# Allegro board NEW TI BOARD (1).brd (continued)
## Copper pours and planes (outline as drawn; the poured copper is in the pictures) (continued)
N992164 on BOTTOM: 186.56,55.23 180.89,55.23 180.89,55.22 180.23,55.22 178.93,53.93 177.18,53.93 177.12,53.87 177.12,52.4 177.15,52.37 178.51,52.37 180.87,54.72 186.52,54.72 186.56,54.76 186.56,55.22
N992182 on BOTTOM: 186.12,59.55 183.29,56.71 175.18,56.71 175.11,56.64 175.11,55.3 175.16,55.26 179.79,55.26 180.05,55.52 186.53,55.52 186.57,55.56 186.57,56.49 188.06,57.99 189.26,57.99 189.52,58.25 189.52,59.08 189.06,59.55
N992267 on BOTTOM: 186.56,54.43 181.51,54.43 175.12,48.03 175.12,42.94 175.2,42.85 176.59,42.85 176.73,42.99 176.73,48.58 182.08,53.92 186.55,53.92 186.56,53.94 186.56,54.42
N992271 on BOTTOM: 179.11,43.16 178.93,43.34 178.93,50.11 180.78,51.96 181.13,51.96 181.36,51.73 181.36,51.49 180.5,50.63 180.5,48.64 180.5,48.64 180.5,43.28 180.39,43.16
N995338 on BOTTOM: 200.92,79.63 199.66,79.63 199.59,79.56 199.59,77.22 198.84,76.46 198.84,75.02 198.9,74.96 200.16,74.96 200.34,75.14 200.34,76.95 201.16,77.77 202.86,77.77 202.93,77.84 202.93,79.19 202.87,79.25 201.3,79.25
N1047887 on BOTTOM: 160.3,118.97 160.42,119.09 160.42,123.73 160.36,123.79 158.4,123.79 158.25,123.64 158.25,118.98 158.26,118.97
N1057020 on BOTTOM: 156.36,122.46 157.13,121.69 157.13,118.88 158.37,117.64 160.83,117.64 162.38,116.09 162.38,111.26 162.2,111.07 161.12,111.07 160.76,111.43 160.76,114.91 160,115.66 157.86,115.66 157.59,115.39 157.56,115.39 157.34,115.17 157.34,108.06 158.72,106.68 158.72,104.86 157.9,104.04 153.38,104.04 151.81,105.62 151.81,120.77 153.49,122.46
N1102671 on TOP: 177.74,114.29 177.74,109.54 176.68,108.48 175.38,108.48 175.07,108.79 175.07,114.39 175.07,114.39 175.3,114.62 177.41,114.62
N1102671 on TOP: 167.86,114.25 168.24,114.25 168.26,114.27 171.12,114.27 171.6,113.79 171.6,109.76 160.92,99.07 155.56,99.07 154.84,99.79 154.84,101.93 155.25,102.35 158.66,102.35 167.09,110.78 167.09,113.48
N1102671 on BOTTOM: 172.2,115.91 174.33,115.91 175.01,115.23 175.01,108.8 175.46,108.35 176.41,108.35 177,108.94 177,119.24 176.81,119.43 170.73,119.43 169.32,118.03 167.36,118.03 167.22,117.89 167.22,110.31 168.23,109.3 170.53,109.3 171.6,110.37 171.6,115.32
N1232683 on BOTTOM: 153.02,65.88 153.32,66.19 161.42,66.19 161.43,66.18 163.11,66.18 165.69,63.61 165.69,61.92 169.6,61.92 169.68,62 169.68,63.21 169.47,63.41 167.96,63.41 163.69,67.68 151.07,67.68 151.07,67.68 148.77,67.68 148.51,67.42 148.51,66.07 148.7,65.88
N1232719 on BOTTOM: 162.55,62.73 162.55,62.73 164.07,61.21 164.07,56.91 165.53,55.45 165.53,46.62 165.86,46.29 167.3,46.29 167.39,46.38 167.39,47.67 167.12,47.93 167.12,56.73 167.01,56.84 165.34,56.84 165.14,57.04 165.14,57.05 164.86,57.32 164.86,62.12 161.93,65.05 160.55,65.05 160.46,64.96 160.46,63.54 160.59,63.41 161.87,63.41
N1232753 on BOTTOM: 164.5,40.91 167.39,40.91 167.63,41.15 167.63,42.3 167.33,42.6 164.92,42.6 163.3,44.21 163.3,59.76 160.18,62.88 155.66,62.88 155.39,63.15 155.39,64.89 155.39,64.97 155.14,65.21 151.29,65.21 151.03,64.96 148.65,64.96 148.53,64.84 148.53,63.39 148.65,63.27 152.29,63.27 152.3,63.26 153.87,63.26 155.21,61.92 159.38,61.92 162.2,59.1 162.2,43.21
N1262247 on BOTTOM: 182.44,60.36 182.44,59.01 182.54,58.91 183.91,58.91 185.37,60.37 189.61,60.37 190.24,59.74 190.86,59.74 191.28,60.16 191.28,60.89 190.69,61.49 183.57,61.49
N1271766 on BOTTOM: 159.87,65.06 156,65.06 155.87,64.93 155.87,63.58 155.97,63.47 159.82,63.47 159.92,63.58 159.92,65
N1473058 on BOTTOM: 202.38,104.88 202.38,103.47 202.38,103.47 202.38,103.01 202.6,102.79 204.48,102.79 205.16,103.47 206.09,103.47 206.81,102.75 208.39,102.75 209,103.36 209,104.31 208.42,104.9 205.76,104.9 205.75,104.91 205.02,104.91 204.63,105.29 202.79,105.29
N1473062 on BOTTOM: 204.64,101.51 204.57,101.58 202.54,101.58 202.29,101.33 202.29,98.12 201.9,97.73 201.9,95.28 202.04,95.14 203.99,95.14 204.04,95.19 204.04,98.35 204.64,98.95
N1473074 on BOTTOM: 210.48,114.22 208.05,114.22 207.88,114.05 207.88,110.66 207.88,110.66 207.88,110.37 206.7,109.19 206.29,108.78 206.29,106.23 206.81,105.71 208.47,105.71 208.97,106.21 208.97,108.29 209.6,108.91 211.98,108.91 212.11,109.05 212.11,112.59 210.99,113.71 210.99,113.71
N1473136 on BOTTOM: 210.51,102.73 209.82,102.03 206.49,102.03 206.15,101.69 206.15,100.35 206.89,99.61 209.54,99.61 209.94,99.21 211.05,99.21 211.13,99.29 211.13,100.32 212.07,101.26 212.07,108.27 212.02,108.32 210.59,108.32 210.51,108.24
N1473188 on BOTTOM: 210.12,97.19 210.16,97.23 210.16,98.24 210.12,98.28 208.79,98.28 208.28,98.28 205.54,95.53 205.54,94.25 205.62,94.17 207.04,94.17 207.13,94.25 207.13,95.7 208.62,97.19
N1473270 on BOTTOM: 211.28,98.23 211.2,98.15 211.2,96.81 211.2,96.36 210.5,95.65 208.09,95.65 208,95.57 208,94.3 208.17,94.13 211.97,94.13 212.14,94.3 212.14,98.15 212.06,98.23
N1626311 on BOTTOM: 40.76,67.2 42.36,67.2 42.44,67.11 42.44,63.68 42.85,63.27 49.2,63.27 50.43,62.04 50.43,61.16 50.43,60.42 51.84,59.01 51.84,52.03 50.84,51.03 49.37,51.03 48.58,51.83 48.58,61.16 48.57,61.16 48.57,61.47 47.89,62.15 42.6,62.15 41.85,61.4 40.69,61.4 40.03,62.06 40.03,63.18 40.58,63.73 40.58,67.02
N1626403 on BOTTOM: 63.81,41.53 62.79,41.53 62.08,40.83 62.08,37.66 64.21,35.53 66.57,35.53 66.71,35.68 66.71,38.08 66.51,38.28 65.53,38.28 64.5,39.32 64.5,40.84
N1626473 on BOTTOM: 47.07,49.95 44.81,49.95 44.12,49.26 44.12,44.6 44.21,44.51 46.4,44.51 46.97,45.07 50.99,45.07 51.53,45.61 51.53,46.93 50.92,47.54 48.87,47.54 47.19,49.22 47.19,49.82
N1626717 on BOTTOM: 39.41,67.21 37.88,67.21 37.59,66.92 37.59,65.48 37.17,65.06 35.08,65.06 34.96,64.94 34.96,63.23 35.07,63.12 37.41,63.12 39.5,65.21 39.5,67.11
N1626863 on BOTTOM: 48.5,38.59 47.55,38.59 47.34,38.38 47.34,36.7 47.24,36.6 47.24,34.74 47.29,34.68 48.97,34.68 49.07,34.78 49.07,36.53 48.66,36.95 48.66,38.43
N1626895 on BOTTOM: 45.99,34.65 44.28,34.65 44.18,34.75 44.18,36.93 45.25,38 46.13,38 46.46,37.68 46.46,36.95 46.08,36.58 46.08,34.74
N1626895 on BOTTOM: 41.37,42.66 37.66,42.66 37.59,42.73 36.99,42.73 36.81,42.55 36.81,42.05 37.09,41.77 37.52,41.77 37.71,41.96 41.36,41.96 41.41,42.01 41.41,42.62
N1626923 on BOTTOM: 42.38,43.93 39.24,43.93 39.18,43.87 39.18,43.29 39.23,43.24 42,43.24 42.27,42.97 42.27,41.87 41.16,40.76 41.16,37.85 40.99,37.67 40.99,36.31 41.07,36.24 42.51,36.24 42.66,36.39 42.66,41.3 42.98,41.62 42.98,43.33
N1627019 on BOTTOM: 41.71,49.26 37.81,49.26 37.69,49.14 37.69,47.99 39.17,46.51 39.17,45.89 39.24,45.81 41.34,45.81 41.49,45.96 41.49,47.49 41.8,47.8 41.8,49.18
N1627749 on BOTTOM: 55.24,48.03 53.49,48.03 53.35,47.88 53.35,44.95 53.88,44.41 55.18,44.41 55.41,44.63 55.41,47.87
N1658391 on TOP: 121.04,68.6 121.02,68.61 121.02,82.91 120.54,83.38 116.42,83.38 115.75,82.72 115.75,74.2 115.69,74.15 115.69,66.36 115.7,66.35 114.83,65.48 114.83,61.22 115.62,60.43 117.04,60.43 117.05,60.43 117.57,60.43 118.31,61.18 118.31,63.74 121.04,66.47
N1658391 on BOTTOM: 120.17,83.01 117.73,83.01 116.7,81.98 116.7,71.79 115.51,70.61 114.04,70.61 113.91,70.47 113.91,68.12 113.91,62.09 115.7,60.3 116.71,60.3 116.71,60.31 117.26,60.31 118.33,61.38 118.33,63.63 121.29,66.58 121.29,69.28 121.29,69.28 121.29,81.89
N1674736 on BOTTOM: 94.68,54.57 93.32,54.57 93.23,54.48 93.23,53.09 93.46,52.86 97.12,52.86 97.17,52.91 97.17,53.92 97.02,54.07 95.17,54.07
N1674945 on BOTTOM: 112.13,60.6 111.16,60.6 111.08,60.52 111.08,59.34 111.17,59.24 112.14,59.24 113.2,58.18 113.2,57.75 113.32,57.64 114.66,57.64 114.78,57.75 114.78,58.94 114.53,59.19 113.54,59.19
N1675432 on BOTTOM: 92.97,93.77 90.76,93.77 90.58,93.59 90.58,89.49 90.76,89.31 92.16,89.31 92.32,89.47 92.32,91.08 93.07,91.82 93.07,93.67
N1687940 on BOTTOM: 60.23,108.31 61.8,109.88 61.8,114.74 62.16,115.1 63.22,115.1 63.56,114.77 63.56,110.69 64.45,109.8 73.72,109.8 75.13,111.2 75.13,114.82 75.33,115.02 76.53,115.02 76.77,114.79 76.77,110.51 76.86,110.51 77.42,109.96 85.99,109.96 86.88,110.84 86.88,114.21 86.86,114.22 87.46,114.82 88.57,114.82 88.94,114.45 88.94,111.14 89.54,110.53 91.96,110.53 92.38,110.95 92.38,114.65 92.64,114.91 93.77,114.91 94.04,114.64 94.04,109.96 89.91,105.82 72.39,105.82 62.62,96.05 56.46,96.05 53.96,98.55 53.96,106.91 55.36,108.31
N1688282 on TOP: 22.72,60.34 19,60.34 18.42,59.76 18.42,58.08 26.79,49.71 29.61,49.71 30.62,50.72 30.62,52.44
N1688282 on BOTTOM: 1.1,50.5 1.52,50.08 5.71,50.08 6.3,49.49 30.05,49.49 30.8,50.24 30.8,52.05 30.39,52.46 30.39,55.65 25.8,60.24 20.2,60.24 19.23,59.27 19.23,57.25 23.35,53.12 23.35,52.77 23.05,52.46 6.91,52.46 5.29,54.08 1.28,54.08 1.1,53.9
N1688286 on TOP: 22.72,68.64 19.33,68.64 17.24,70.73 17.24,77.99 14.04,81.19 14.04,100.12 18.28,104.36 25.93,104.36 33.29,111.72 33.29,115.33 33.94,115.98 36.63,115.98 36.95,115.66 36.95,111.65 26.83,101.53 20.6,101.53 18.69,99.62 18.69,83 25.15,76.54 25.15,71.08
N1688286 on BOTTOM: 31.28,76.83 22.71,76.83 18.81,72.93 18.81,69.65 19.74,68.72 22.39,68.72 27.38,73.71 31.25,73.71 31.36,73.82 31.36,76.76
N1688354 on TOP: 3.93,48.74 1.07,48.74 0.45,48.12 0.45,34.28 1.11,33.62 4.65,33.62 5.13,34.11 5.13,37.68 3.5,39.31 3.5,45.3 4.47,46.27 4.47,48.2
N1688414 on TOP: 24.56,115.18 24.56,110.5 23.44,109.38 5.99,109.38 0.92,104.31 0.92,74.8 7.57,68.15 11.55,68.15 13.19,69.79 13.19,75.27 4.72,83.74 4.72,101.18 9.7,106.15 24.37,106.15 29.7,111.48 29.7,115.19 29.03,115.86 25.25,115.86
N1688414 on BOTTOM: 30.96,81.41 11.36,81.41 7.42,77.47 7.42,69.87 8.76,68.53 11.46,68.53 12.59,69.66 12.59,75.62 14.93,77.96 31.12,77.96 31.32,78.16 31.32,81.05
N1688502 on BOTTOM: 79.07,125.12 74.99,125.12 74.23,125.88 72.56,125.88 72.46,125.79 72.46,124.5 72.53,124.43 74.01,124.43 74.05,124.47 79.06,124.47 79.09,124.5 79.09,125.11
N1688572 on TOP: 41.42,115.91 39.43,113.92 39.43,111.15 29,100.72 28.99,100.72 27.29,99.01 22.35,99.01 21.37,98.04 21.37,84.66 21.84,84.19 30.28,84.19 31.33,85.24 31.33,99.52 34.62,102.81 47.77,102.81 48.24,103.28 48.24,114.71 47.04,115.91
N1688572 on BOTTOM: 47.23,101.6 45.62,101.6 45.09,102.13 45.09,109.54 45.09,109.54 45.09,110.02 51.22,116.15 51.22,117.69 51.43,117.89 52.81,117.89 52.92,117.78 52.92,115.42 47.55,110.05 47.55,101.93
N1688600 on BOTTOM: 102.41,119.46 100.73,119.46 100.61,119.33 100.61,117.19 99.22,115.81 99.22,114.23 99.37,114.08 101.01,114.08 102.46,115.53 102.46,119.4
N1688684 on BOTTOM: 79.06,126.41 76.36,126.41 75.3,127.48 58.81,127.48 51.28,119.95 51.28,118.68 51.42,118.54 52.82,118.54 59.68,125.41 69.03,125.41 69.28,125.15 71.05,125.15 71.21,125.31 71.21,125.91 71.96,126.65 74.87,126.65 75.78,125.74 79.02,125.74 79.09,125.8 79.09,126.38
N1688798 on BOTTOM: 77.19,129.77 75.87,129.77 75.76,129.66 75.76,128.12 76.89,126.99 79.03,126.99 79.11,127.06 79.11,127.61 77.21,129.51 77.21,129.74
N1688806 on BOTTOM: 84.54,130.66 84.54,129.29 82.93,127.68 81.88,127.68 81.82,127.62 81.82,127.08 81.89,127.01 84.5,127.01 84.73,126.78 86.06,126.78 86.13,126.85 86.13,128.28 86.12,128.29 86.13,128.3 86.13,130.68 86.05,130.76 84.65,130.76
N1688834 on TOP: 29.41,44.64 28.07,44.64 23.86,40.44 13.59,40.44 12.62,39.47 12.62,35.41 14.48,33.55 31.19,33.55 31.68,34.04 31.68,42.37
N1688870 on TOP: 24.96,44.57 16.24,44.57 7.9,52.9 7.9,58.38 9.8,60.27 11.77,60.27 12.89,59.16 12.89,54.69 19.66,47.92 24.8,47.92 25.41,47.3 25.41,45.02
N1688976 on BOTTOM: 99.33,119.49 94.98,119.49 94.81,119.32 94.81,117.68 94.99,117.5 99.23,117.5 99.43,117.7 99.43,119.4
N1689262 on BOTTOM: 86.7,129.5 86.92,129.28 90.64,129.28 90.69,129.33 90.69,130.68 90.61,130.76 86.73,130.76 86.7,130.74
N1689566 on BOTTOM: 35.88,80.76 33.87,80.76 33.65,80.54 33.65,74.09 33.97,73.77 35.83,73.77 36.16,74.1 36.16,80.48
N1689570 on BOTTOM: 84.22,126.41 81.9,126.41 81.84,126.34 81.84,125.81 81.91,125.74 84.26,125.74 85.21,124.79 85.21,119.5 87.25,117.45 93.53,117.45 93.67,117.6 93.67,119.33 93.55,119.45 91.9,119.45 90.83,118.38 87.54,118.38 86.93,118.99 86.93,123.34 86.63,123.64 86.63,125.67 86.05,126.25 84.38,126.25
N1689690 on BOTTOM: 63.07,85.66 58.49,85.66 58.28,85.45 58.28,83.81 58.43,83.66 62.98,83.66 63.16,83.84 63.16,85.57
N1689742 on BOTTOM: 69.12,85.57 64.51,85.57 64.31,85.38 64.31,83.83 64.47,83.68 69.12,83.68 69.23,83.78 69.23,85.47
N1704443 on TOP: 74.2,116.14 74.2,111.8 73.92,111.52 72.91,111.52 72.59,111.84 72.59,114.92 71.42,116.09 62.1,116.09 61.03,115.02 61.03,111.8 60.63,111.41 59.26,111.41 58.84,111.83 58.84,115.7 60.62,117.48 72.86,117.48
N1704443 on BOTTOM: 72.59,117.49 71.29,117.49 71.15,117.34 71.15,114.86 70.97,114.68 70.97,112.35 70.83,112.21 70.8,112.21 70.8,110.92 70.98,110.74 72.66,110.74 74.2,112.28 74.2,114.52 72.63,116.09 72.63,117.45
N1706830 on BOTTOM: 65.02,119.73 65.02,119.73 65.12,119.63 67.52,119.63 67.52,119.63 68.58,119.63 70,118.21 73.9,118.21 74.98,117.13 76.29,117.13 76.43,117.27 76.43,118.48 76.21,118.71 74.38,118.71 73.85,119.24 69.93,119.24 68.94,120.23 68.45,120.23 68.39,120.29 68.39,120.63 68.23,120.79 65.07,120.79 65.02,120.74
N1706858 on TOP: 68.16,122.72 67.47,122.72 67.15,122.4 67.15,118.18 67.38,117.94 68.21,117.94 68.39,118.12 68.39,122.48
N1706858 on BOTTOM: 66.01,117.73 66.48,117.26 67.85,117.26 69.16,115.95 70.44,115.95 70.56,116.07 70.56,117.26 70.36,117.46 69.3,117.46 68.44,118.33 68.44,118.5 68,118.93 67.57,118.93 67.4,118.77 66.04,118.77 66.01,118.74
N1706992 on BOTTOM: 70.28,114.82 68.84,114.82 68.58,115.08 67.16,115.08 67.11,115.03 67.11,113.98 67.85,113.24 70.31,113.24 70.35,113.28 70.35,114.76
N1707045 on BOTTOM: 84,123.87 81.89,123.87 81.83,123.8 81.83,120.53 80.01,118.71 77.19,118.71 77.06,118.58 77.06,117.18 77.18,117.06 80.29,117.06 84.04,120.82 84.04,123.83
N1707984 on BOTTOM: 73.38,121.34 71.93,121.34 71.57,121.7 69.42,121.7 69.29,121.57 69.29,120.87 69.4,120.76 71.17,120.76 72.12,119.81 73.42,119.81 73.52,119.91 73.52,121.2
N1708918 on TOP: 117.55,93.58 122.99,93.58 125.01,91.55 125.01,70.87 128.83,67.05 128.83,56.04 129.83,55.04 133.6,55.04 135.18,56.62 135.18,70.83 133.39,72.63 133.39,97.34 121.44,109.29 117.86,109.29 116.76,108.19 116.76,94.36
N1744379 on BOTTOM: 80.52,100.01 76.58,100.01 76.37,99.8 76.37,98.38 76.64,98.12 80.48,98.12 80.7,98.34 80.7,99.83
N1744386 on BOTTOM: 81.69,74.26 77.54,74.26 77.4,74.12 77.4,72.53 77.6,72.34 81.78,72.34 81.91,72.46 81.91,74.04
N1751354 on BOTTOM: 108.3,90.09 104.47,90.09 104.42,90.04 104.42,89.37 104.45,89.34 108.85,89.34 109.18,89.67 109.68,89.67 109.68,89.66 110.38,89.66 110.55,89.83 110.55,91.51 110.4,91.66 108.78,91.66 108.68,91.56 108.68,91.51 108.68,91.5 108.68,90.46
N1761027 on BOTTOM: 47.35,61.3 45.71,61.3 44.42,60 44.42,52.31 44.49,52.25 47,52.25 47.21,52.46 47.21,55.1 47.54,55.43 47.54,61.11
N9920271 on BOTTOM: 176.65,42.25 175.13,42.25 175,42.12 175,40.04 177.39,37.65 178.03,37.65 178.05,37.67 186.06,37.67 186.37,37.36 187.65,37.36 188.08,37.78 188.08,38.62 187.84,38.86 177.95,38.86 176.68,40.13 176.68,42.22
N9920531 on BOTTOM: 189.59,39.67 191.88,37.39 192.8,37.39 193.11,37.69 193.11,38.65 191.14,40.62 181.16,40.62 180.49,41.29 180.49,42.51 180.43,42.57 179.08,42.57 178.93,42.42 178.93,41.25 179.09,41.09 179.1,41.09 180.52,39.67

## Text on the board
Ref Des/Silkscreen Top: RED | BLUE | VDD | SCK | SDA | GND
BODY_CENTER: FIGURE | FINISHED_SIZE | 0.5 | 0.7 | 0.8 | 0.9 | 1.0 | 1.016 | 1.2 | 1.3 | 1.4 | 1.8 | 2.0 | 4.0 | 8.5 | 2.5 | 1.5x1.2 | BY LAYER: TOP to BOTTOM | ALL UNITS ARE IN MILLIMETERS | PLATED | NON-PLATED | QTY | 181 | 4 | 2 | 3 | 32 | 6 | 21 | 12 | 26 | 5 | 1 | 8 | 358 | TOTAL HOLES:
